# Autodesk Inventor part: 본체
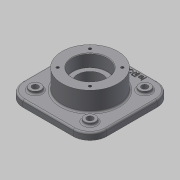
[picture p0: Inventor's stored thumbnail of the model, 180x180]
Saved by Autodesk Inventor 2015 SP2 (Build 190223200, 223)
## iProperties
Created: 2015-07
Part Number: 본체
Material: 일반
Document SubType Name: Modeling
Designer: AMC
Density: 1 g/cm^3
Appearance: 기본값
Author: AMC
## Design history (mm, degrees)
sketch "스케치1"
  geometry: L1 (-75, -75)-(75, -75); L2 (75, -75)-(75, 75); L3 (75, 75)-(-75, 75); L4 (-75, 75)-(-75, -75); L5 (-75, -75)-(75, 75); L6 (75, -75)-(-75, 75); 1 further point
  constraints: 12 end point, 2 midpoint, 2 parallel, 1 horizontal, 1 perpendicular
  dimensions: "d0" = 150 distance of L3.end L2.end; "d1" = 150 distance of L2.end L1.end
extrude "돌출1" new body sketch "스케치1" distance "d2" = 12; taper "d3" = 0 deg
sketch "스케치2"
  geometry: C1 r 50 at (0, 0); 1 further point
  constraints: 1 centre point, 1 coincident
  dimensions: "d4" = 100 diameter of C1
extrude "돌출2" join sketch "스케치2" distance "d5" = 47; taper "d7" = 0 deg; dims "d6" = 23, "d8" = 0
hole "구멍1" diameter "d11" = 45; stored, may be unused: countersink angle "d15" = 90 deg, drill point angle "d17" = 0 deg; dims "d12" = 6, "d13" = 62, "d14" = 22, "d16" = 8, "d111" = 10, "d112" = 10
hole "구멍2" diameter "d22" = 62; stored, may be unused: countersink angle "d26" = 90 deg, drill point angle "d28" = 0 deg; dims "d23" = 6, "d24" = 62, "d25" = 22, "d27" = 22, "d113" = 10, "d114" = 10
sketch "스케치3"
  geometry: L1 (-49, -49)-(49, -49); L2 (49, -49)-(49, 49); L3 (49, 49)-(-49, 49); L4 (-49, 49)-(-49, -49); L5 (-49, -49)-(49, 49); L6 (49, -49)-(-49, 49); C1 r 10 at (-49, 49); C2 r 10 at (49, 49); C3 r 10 at (-49, -49); C4 r 10 at (49, -49); 1 further point
  constraints: 12 end point, 4 centre point, 4 coincident, 2 midpoint, 2 parallel, 1 horizontal, 1 perpendicular
  dimensions: "d29" = 98 distance of L3.end L2.end; "d30" = 98 distance of L2.end L1.end; "d31" = 20 diameter of C1; "d32" = 20 diameter of C2; "d33" = 20 diameter of C3; "d34" = 20 diameter of C4
extrude "돌출3" join sketch "스케치3" distance "d35" = 5; taper "d36" = 0 deg
hole "구멍3" diameter "d39" = 11; stored, may be unused: countersink angle "d43" = 90 deg, drill point angle "d45" = 118 deg; dims "d37" = 10, "d38" = 10, "d40" = 6, "d41" = 62, "d42" = 22, "d44" = 22
hole "구멍4" diameter "d48" = 11; stored, may be unused: countersink angle "d52" = 90 deg, drill point angle "d54" = 118 deg; dims "d46" = 10, "d47" = 10, "d49" = 6, "d50" = 62, "d51" = 22, "d53" = 22
hole "구멍5" diameter "d57" = 11; stored, may be unused: countersink angle "d61" = 90 deg, drill point angle "d63" = 118 deg; dims "d55" = 10, "d56" = 10, "d58" = 6, "d59" = 62, "d60" = 22, "d62" = 22
hole "구멍6" diameter "d66" = 11; stored, may be unused: countersink angle "d70" = 90 deg, drill point angle "d72" = 118 deg; dims "d64" = 10, "d65" = 10, "d67" = 6, "d68" = 62, "d69" = 22, "d71" = 22
sketch "스케치4"
  geometry: L1 (0, 0)-(28.991, 28.991); L2 (0, 0)-(41, 0); C1 r 41 at (0, 0); 2 further points
  constraints: 4 end point, 2 coincident, 1 centre point, 1 equal length, 1 horizontal
  dimensions: "d73" = 82 diameter of C1; "d74" = 41 distance of L1.start L1.end; "d75" = 45 deg angle of L2 L1
hole "구멍7" sketch "스케치4" at (28.991, 28.991) diameter "d76" = 4.917; stored, may be unused: countersink angle "d80" = 90 deg, drill point angle "d82" = 118 deg; dims "d77" = 10, "d78" = 62, "d79" = 22, "d81" = 13
sketch "스케치5"
  geometry: L1 (0, 0)-(28.991, 28.991); L2 (0, 0)-(41, 0); C1 r 41 at (0, 0); 2 further points
  constraints: 4 end point, 2 coincident, 1 centre point, 1 equal length, 1 horizontal
  dimensions: "d86" = 82 diameter of C1; "d87" = 41 distance of L1.start L1.end; "d88" = 45 deg angle of L2 L1
hole "구멍8" sketch "스케치5" at (28.991, 28.991) diameter "d89" = 4.917; stored, may be unused: countersink angle "d93" = 90 deg, drill point angle "d95" = 118 deg; dims "d90" = 10, "d91" = 62, "d92" = 22, "d94" = 13
fillet "모깎기1" dims "d99" = 3
fillet "모깎기2" dims "d100" = 0.3
chamfer "모따기1" distance "d101" = 1; stored, may be unused: second distance "d102" = 2, angle "d103" = 45 deg
fillet "모깎기3" dims "d104" = 30
sketch "스케치7"
  geometry: 2 further points
  constraints: 1 other
  dimensions: "d108" = 65 vertical distance of point (0, 0) point (0.255, 65)
feature "엠보싱2" sketch "스케치7" dims "d0" = 150, "d1" = 150, "d29" = 98, "d30" = 98, "d31" = 20, "d32" = 20, "d33" = 20, "d34" = 20, "d109" = 1, "d110" = 0
node "솔리드1"
pattern_circular "원형 패턴3" dims angle "d116" = 360 deg
pattern_circular "원형 패턴4" dims angle "d119" = 360 deg
